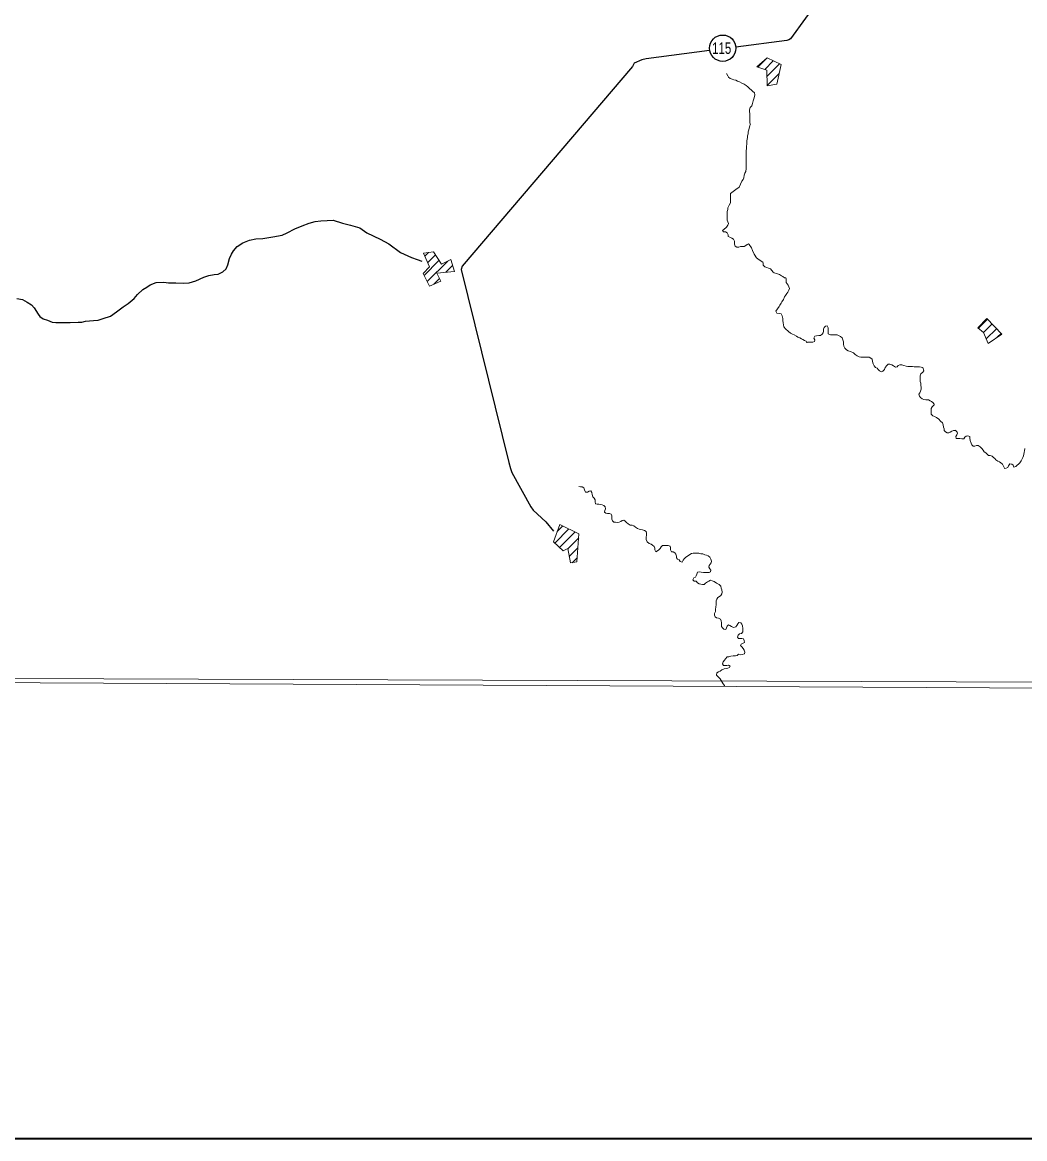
# Model space of a CAD drawing. Extents: x 553962 to 842807, y 8883888 to 9032388.
# Drawn here: x 608778 to 614885, y 8896027 to 8902830 of the extents above; entities that cross this region are included whole.
import ezdxf
from ezdxf.enums import TextEntityAlignment as Align

# ---------------------------------------------------------------- set-up
doc = ezdxf.new("R2010")
doc.units = 0
doc.header["$LTSCALE"] = 200
doc.layers.add('6', color=7, linetype='Continuous', lineweight=13)

msp = doc.modelspace()

# ---------------------------------------------------------------- linework, layer by layer
at = {"layer": '6'}
for p, q in [((613258.9, 8902557.5), (613307.3, 8902605.9)), ((613301.4, 8902543.4), (613353.5, 8902595.5)), ((613314.5, 8902500), (613391.6, 8902577)), ((613315.6, 8902444.5), (613388.7, 8902517.5)), ((611230.3, 8901404.8), (611252.2, 8901426.7)), ((611248, 8901365.9), (611294.8, 8901412.8)), ((611226.5, 8901287.9), (611316.8, 8901378.2)), ((611245.1, 8901249.9), (611370.1, 8901374.9)), ((611358.8, 8901307.1), (611399.5, 8901347.8)), ((611285.4, 8901233.7), (611320.5, 8901268.7)), ((614602.7, 8900965), (614658.4, 8901020.7)), ((614634.6, 8900940.2), (614686, 8900991.7)), ((614651.2, 8900900.4), (614713.6, 8900962.7)), ((613558.2, 8900878.2), (613557.9, 8900877)), ((614718.1, 8900910.6), (614741.2, 8900933.8)), ((612022, 8899656), (612108.6, 8899742.6)), ((612037, 8899727.6), (612070.7, 8899761.3)), ((612051.1, 8899628.6), (612146.6, 8899724)), ((612101.1, 8899622), (612167.9, 8899688.8)), ((612110.5, 8899574.8), (612163.2, 8899627.5)), ((612129.1, 8899536.8), (612158.5, 8899566.2))]:
    msp.add_line(p, q, dxfattribs=at)
at = {"layer": '6', "lineweight": 35}
msp.add_lwpolyline([(574695.3, 8924769.6), (626625.7, 8924769.6), (626625.7, 8896026.7), (574695.3, 8896026.7)], close=True, dxfattribs=at)
at = {"layer": '6'}
for points in [[(618535.2, 8909853.3), (607574.3, 8909890.7), (607543.3, 8898835.3), (618504.2, 8898795.8)], [(613253.6, 8902559.2), (613316.1, 8902613.6), (613400.9, 8902572.5), (613374.3, 8902452.9), (613315.7, 8902442), (613313.8, 8902539.4)], [(611222.2, 8901422.7), (611283.2, 8901431), (611331.4, 8901355.2), (611388, 8901384.1), (611411, 8901311.7), (611304.4, 8901302.2), (611328.1, 8901252.8), (611258.8, 8901221.7), (611220.8, 8901299.8), (611260, 8901339.5)], [(614654.9, 8901024.3), (614599.9, 8900967.2), (614634.5, 8900940.5), (614662.7, 8900873), (614745.5, 8900929.3)], [(612052.6, 8899770.2), (612169.7, 8899712.7), (612156.6, 8899541.5), (612118.4, 8899535), (612101, 8899622.7), (612072.7, 8899608.2), (612013.7, 8899663.8)]]:
    msp.add_lwpolyline(points, close=True, dxfattribs=at)
at = {"layer": '6', "lineweight": 25}
for points in [[(614884.3, 8904031.6), (614289.5, 8903510.2), (613661, 8902994.8), (613641.6, 8902983.7), (613458.3, 8902730.3), (613448.1, 8902723.2), (613436.9, 8902720.2), (613124.7, 8902678.9)], [(612965.8, 8902657.9), (612578.6, 8902606.6), (612553.1, 8902601.6), (612506.2, 8902581.3), (612494.9, 8902560.9), (611458.3, 8901343.3), (611451.1, 8901322.9), (611742.2, 8900146.7), (611753.3, 8900110), (611761.3, 8900086.6), (611876.7, 8899876.5), (611889.9, 8899857.1), (611968.1, 8899786.6), (612014.2, 8899728.6)], [(610201.6, 8901509.7), (610244.4, 8901511.6), (610303.5, 8901523.7), (610360.6, 8901533.8), (610391.2, 8901548), (610438.2, 8901571.4), (610483.1, 8901590.6), (610526, 8901606.9), (610561.7, 8901616), (610597.3, 8901621), (610635, 8901621.9), (610672.7, 8901623.9), (610728.7, 8901605.5), (610777.6, 8901593.2), (610834.6, 8901576.8), (610877.3, 8901548.1), (610958.6, 8901509.3), (611010.5, 8901479.6), (611082.6, 8901426.5), (611149.8, 8901396.9), (611184.3, 8901383.6), (611211.9, 8901373.9)], [(609069.8, 8901001.3), (609118.7, 8901002.2), (609140.1, 8901002.2), (609163.6, 8901008.3), (609211.5, 8901012.2), (609240, 8901014.2), (609271.6, 8901025.4), (609315.5, 8901039.6), (609352.3, 8901066), (609392.1, 8901096.5), (609423.8, 8901115.8), (609460.6, 8901147.3), (609481, 8901171.7), (609511.7, 8901202.2), (609536.2, 8901215.4), (609556.7, 8901230.7), (609593.4, 8901244.9), (609641.3, 8901246.8), (609669.8, 8901242.7), (609712.6, 8901241.6), (609761.5, 8901239.5), (609794.1, 8901241.4), (609835.9, 8901254.6), (609883.9, 8901277.9), (609914.5, 8901287.1), (609947.1, 8901294.1), (609970.6, 8901296.1), (609999.1, 8901310.3), (610019.6, 8901328.6), (610029.9, 8901353.1), (610040.2, 8901389.7), (610053.5, 8901416.2), (610064.8, 8901436.6), (610086.3, 8901463), (610122.1, 8901486.4), (610161.8, 8901501.6), (610201.6, 8901509.7)], [(608745.3, 8901147.6), (608778.9, 8901141.4), (608808.4, 8901124), (608833.8, 8901107.7), (608851.1, 8901089.3), (608874.4, 8901051.6), (608884.5, 8901036.3), (608905.9, 8901024), (608932.3, 8901014.8), (608959.8, 8901002.5), (608982.2, 8901001.5), (609069.8, 8901001.3)]]:
    msp.add_lwpolyline(points, dxfattribs=at)
at = {"layer": '6'}
for points in [[(613067.8, 8902517.8), (613076.8, 8902504.5), (613080.8, 8902495.3), (613091, 8902488.1), (613102.1, 8902483.9), (613113.3, 8902479.8), (613124.5, 8902476.7), (613134.6, 8902471.5), (613147.8, 8902467.4), (613162, 8902460.2), (613175.2, 8902452.9), (613187.3, 8902444.7), (613197.4, 8902436.5), (613210.6, 8902425.2), (613218.7, 8902418.1), (613227.7, 8902409.8), (613238.9, 8902399.6), (613241.8, 8902388.4), (613236.6, 8902370.1), (613231.4, 8902351.8), (613226.2, 8902335.5), (613223.1, 8902321.3), (613212.8, 8902310.1), (613208.7, 8902296.9), (613208.6, 8902286.7), (613210.5, 8902272.5), (613210.5, 8902262.3), (613210.3, 8902245), (613210.2, 8902232.7), (613210.2, 8902220.5), (613213.1, 8902210.3), (613215.1, 8902208.5)], [(613214.9, 8902208.8), (613211.4, 8902200.8), (613205.1, 8902175.3), (613200.9, 8902162.1), (613199.8, 8902149.9), (613195.7, 8902138.7), (613195.6, 8902128.6), (613192.4, 8902108.2), (613192.3, 8902087.8), (613191.2, 8902074.6), (613191.1, 8902061.3), (613187.9, 8902046.1), (613187.8, 8902034.9), (613187.8, 8902023.7), (613188.9, 8902003.7), (613187.6, 8901993.1), (613187.5, 8901980.9), (613187.4, 8901965.6), (613188.3, 8901951.4), (613189.2, 8901939.2), (613185.5, 8901921), (613180.9, 8901911.7), (613176.7, 8901899.5), (613173.6, 8901882.2), (613169.4, 8901872.1), (613162.2, 8901861.9), (613144.8, 8901826.3), (613125.2, 8901810.6), (613093.6, 8901785.9), (613093.5, 8901775.8), (613092.4, 8901763.5), (613092.3, 8901753.4), (613092.2, 8901743.2), (613092.2, 8901730.9), (613083.9, 8901714.7), (613076.7, 8901698.5), (613075.6, 8901688.3), (613072.5, 8901676.1), (613072.4, 8901663.9), (613072.2, 8901647.6), (613072.2, 8901635.3), (613072.1, 8901625.2), (613077.1, 8901614.9), (613080.1, 8901604.7), (613077, 8901594.6), (613067.7, 8901581.4), (613051.4, 8901568.2), (613043.2, 8901562.2), (613050.2, 8901554), (613062.5, 8901553.9), (613071.6, 8901546.7), (613077.6, 8901534.5), (613078.5, 8901524.3), (613088.7, 8901520.2), (613100.8, 8901515), (613111, 8901508.8), (613117, 8901495.5), (613116.8, 8901478.2), (613120.8, 8901464.9), (613131, 8901459.8), (613143.2, 8901460.7), (613153.4, 8901463.7), (613164.6, 8901463.7), (613175.8, 8901464.6), (613186, 8901470.7), (613194.2, 8901476.7), (613203.3, 8901480.7)], [(613203.3, 8901480.7), (613207.5, 8901475.3), (613220.8, 8901455), (613227, 8901438.8), (613237.3, 8901416.4), (613250.6, 8901395.1), (613268, 8901382.9), (613288.8, 8901367.7)], [(613288.8, 8901367.7), (613291.1, 8901363.5), (613291.6, 8901350.4), (613301.8, 8901340.3), (613337.5, 8901327.3), (613352.9, 8901307), (613358, 8901304), (613372.2, 8901300), (613390.6, 8901292.9), (613402.8, 8901284.9)], [(613402.8, 8901284.9), (613412.2, 8901280.8), (613421.3, 8901273.6), (613429.4, 8901273), (613432.2, 8901268.8), (613432.3, 8901265)], [(613369.1, 8901070.7), (613389.4, 8901097.2), (613393.5, 8901107.3), (613400.7, 8901118.5), (613405.9, 8901127.6), (613415.1, 8901141.8), (613422.3, 8901156.1), (613428.5, 8901166.2), (613436.8, 8901178.4), (613442.9, 8901186.5), (613449.1, 8901197.7), (613452.2, 8901207.8), (613449.2, 8901219), (613444.2, 8901228.2), (613438.2, 8901236.4), (613431.1, 8901243.6), (613431.2, 8901254.8), (613432.3, 8901265), (613432.3, 8901265)], [(613557.9, 8900877), (613552.9, 8900886.2), (613543.8, 8900891.3), (613533.6, 8900897.5), (613524.5, 8900901.7), (613515.4, 8900906.8), (613503.2, 8900910.9), (613494.1, 8900917.1), (613480.9, 8900925.3), (613469.8, 8900930.5), (613458.6, 8900934.7), (613445.5, 8900945.9), (613428.3, 8900962.3), (613418.2, 8900974.6), (613415.3, 8900985.9), (613413.3, 8900999.1), (613412.4, 8901013.4), (613411.5, 8901025.6), (613408.5, 8901040.9), (613401.5, 8901054.2), (613390.3, 8901055.3), (613375.1, 8901058.4), (613369.1, 8901070.7), (613369.1, 8901072), (613369.1, 8901070.7)], [(614265.5, 8900726.8), (614255.3, 8900728.9), (614245.2, 8900731), (614233, 8900731.1), (614222.8, 8900731.2), (614212.6, 8900731.2), (614201.5, 8900732.3), (614187.2, 8900733.4), (614174, 8900733.5), (614162.8, 8900733.6), (614148.6, 8900737.8), (614136.4, 8900741.9), (614125.2, 8900742), (614115.1, 8900739), (614108.9, 8900730.9), (614097.7, 8900727.9), (614086.6, 8900736.1), (614076.4, 8900742.3), (614064.3, 8900747.5), (614054.1, 8900747.5), (614044.9, 8900739.4), (614034.6, 8900727.3), (614031.5, 8900715.1), (614021.2, 8900703.9), (614012.1, 8900699.9), (613999.9, 8900706.1), (613992.8, 8900714.3), (613985.8, 8900721.5), (613976.6, 8900725.6), (613968.6, 8900735.8), (613961.5, 8900748.1), (613957.6, 8900762.4), (613955.6, 8900776.7), (613948.6, 8900783.8), (613937.4, 8900790), (613924.2, 8900790.1), (613914, 8900790.2), (613899.8, 8900790.3), (613886.6, 8900790.3), (613876.4, 8900792.4), (613865.3, 8900797.6), (613853.1, 8900804.8), (613843, 8900816.1), (613824.8, 8900823.3), (613810.6, 8900827.5), (613799.4, 8900834.7), (613790.3, 8900844.9), (613783.3, 8900856.2), (613780.3, 8900869.4), (613780.4, 8900882.7), (613777.5, 8900894.9), (613772.5, 8900906.2), (613763.4, 8900914.4), (613751.2, 8900920.6), (613742.1, 8900924.7), (613728.9, 8900925.8), (613714.6, 8900925.9), (613701.4, 8900926), (613687.2, 8900932.2), (613687.3, 8900944.4), (613687.4, 8900957.6), (613687.5, 8900968.8), (613681.5, 8900980.1), (613671.3, 8900979.1), (613664.1, 8900971), (613660, 8900960.8), (613658.9, 8900948.6), (613657.8, 8900938.5), (613650.6, 8900929.3), (613641.4, 8900922.3), (613630.2, 8900921.3), (613617, 8900920.4), (613605.8, 8900917.4), (613600.6, 8900905.2), (613605.6, 8900896), (613604.5, 8900885.8), (613595.3, 8900881.8), (613584.1, 8900880.9), (613573, 8900880.9), (613562.8, 8900880), (613558.2, 8900878.2)], [(614333.4, 8900497.8), (614333.4, 8900503.9), (614326.3, 8900512.1), (614318.2, 8900518.3), (614309.1, 8900523.4), (614299, 8900528.6), (614282.7, 8900528.7), (614270.5, 8900531.8), (614261.4, 8900535.9), (614251.3, 8900543.1), (614244.2, 8900552.3), (614241.2, 8900563.6), (614245.4, 8900572.7), (614249.5, 8900581.8), (614254.7, 8900594), (614254.8, 8900605.2), (614252.8, 8900619.5), (614251.9, 8900630.7), (614247.9, 8900640.9), (614248, 8900652.1), (614249.1, 8900664.3), (614249.2, 8900676.6), (614253.3, 8900688.8), (614264.6, 8900698.9), (614270.7, 8900707), (614265.5, 8900726.8)], [(614664.7, 8900190.6), (614656.6, 8900197.8), (614648.6, 8900206), (614637.4, 8900213.2), (614631.4, 8900223.4), (614624.3, 8900233.6), (614613.2, 8900243.9), (614602.1, 8900251.1), (614590.9, 8900251.2), (614580.7, 8900247.2), (614570.5, 8900247.2), (614562.5, 8900255.4), (614559.5, 8900265.6), (614553.5, 8900281.9), (614551.6, 8900296.2), (614551.6, 8900306.4), (614539.4, 8900310.6), (614529.3, 8900308.6), (614521.1, 8900301.5), (614513.9, 8900292.4), (614502.7, 8900292.5), (614490.5, 8900293.6), (614480.3, 8900293.6), (614468.1, 8900293.7), (614466.2, 8900305.9), (614471.3, 8900316.1), (614475.5, 8900326.2), (614473.7, 8900333.3), (614468.3, 8900338.8), (614465.5, 8900344.2), (614462.8, 8900341.5), (614452.2, 8900342.7), (614442, 8900338.7), (614431.8, 8900332.6), (614422.6, 8900327.6), (614412.4, 8900328.7), (614402.3, 8900333.8), (614395.2, 8900342), (614394.3, 8900352.2), (614391.3, 8900363.4), (614389.4, 8900376.7), (614383.4, 8900388.9), (614372.3, 8900400.2), (614361.2, 8900411.5), (614347, 8900420.8), (614334.8, 8900426.9), (614325.7, 8900432.1), (614315.6, 8900442.3), (614315.7, 8900454.6), (614315.8, 8900464.7), (614315.8, 8900477), (614321, 8900486.1), (614329.2, 8900495.2), (614333.4, 8900497.8)], [(614761.4, 8900112.2), (614760.8, 8900116.7), (614753.8, 8900128.9), (614749.8, 8900138.1), (614740.7, 8900146.3), (614731.6, 8900151.5), (614721.4, 8900155.6), (614710.3, 8900162.8), (614704.2, 8900171), (614695.1, 8900178.2), (614686, 8900185.4), (614674.9, 8900190.5), (614664.7, 8900190.6)], [(614885.7, 8900232.8), (614885.7, 8900230.9), (614884.6, 8900220.8), (614882.5, 8900208.6), (614880.4, 8900197.4), (614878.3, 8900187.2), (614874.1, 8900178.1), (614867.9, 8900165.9), (614862.8, 8900156.8), (614854.6, 8900144.6), (614847.4, 8900137.5), (614839.2, 8900130.4), (614831, 8900123.3), (614819.8, 8900119.3), (614814.8, 8900130.6), (614807.7, 8900137.8), (614794.5, 8900138.8), (614787.3, 8900127.7), (614783.2, 8900116.5), (614772, 8900112.5), (614762.4, 8900110.6), (614761.4, 8900112.2)], [(612169.4, 8900000.7), (612179.1, 8899998.2), (612189.2, 8899998.2), (612198.4, 8899993), (612202.4, 8899980.8), (612208.4, 8899967.5), (612220.6, 8899966.4), (612230.8, 8899972.4), (612242, 8899974.4), (612249, 8899964.2), (612251, 8899951.9), (612254, 8899938.7), (612263.1, 8899930.5), (612269.1, 8899919.2), (612269, 8899907), (612270.9, 8899894.8), (612281.1, 8899892.7), (612291.3, 8899892.6), (612301.4, 8899891.5), (612311.6, 8899889.4), (612320.7, 8899885.3), (612328.8, 8899877.1), (612330.8, 8899865.9), (612326.6, 8899855.7), (612325.5, 8899845.5), (612333.6, 8899839.3), (612343.8, 8899836.2), (612356, 8899836.2), (612365.1, 8899832), (612369.1, 8899822.8), (612369.1, 8899812.6), (612369, 8899801.4), (612374, 8899791.2), (612381.1, 8899784), (612391.2, 8899782.9), (612403.4, 8899781.8), (612414.6, 8899784.8), (612424.8, 8899787.8), (612433, 8899793.9), (612443.2, 8899796.9), (612451.3, 8899790.7), (612458.4, 8899782.5), (612468.5, 8899773.3), (612480.6, 8899765.1), (612493.8, 8899765), (612504, 8899760.8), (612514.1, 8899752.6), (612526.2, 8899745.4), (612535.4, 8899741.3), (612545.5, 8899738.2), (612556.7, 8899738.1), (612567.9, 8899733.9), (612578, 8899726.7), (612581, 8899716.5), (612580.9, 8899704.3), (612579.8, 8899692.1), (612578.7, 8899678.8), (612585.7, 8899664.5), (612597.8, 8899654.3), (612609, 8899649.1), (612617.1, 8899642.9), (612628.2, 8899634.7), (612632.2, 8899625.5), (612632.2, 8899614.3), (612638.2, 8899603.1), (612648.4, 8899609.1), (612655.6, 8899616.2), (612663.8, 8899623.3), (612669.9, 8899633.4), (612679.2, 8899642.6), (612691.4, 8899642.5), (612702.5, 8899641.4), (612713.7, 8899641.3), (612724.9, 8899637.2), (612727.9, 8899626.9), (612727.8, 8899614.7), (612732.8, 8899602.5), (612743, 8899602.4), (612753.1, 8899597.2), (612759.1, 8899589.1), (612763.1, 8899576.8), (612764.1, 8899566.6), (612770.1, 8899558.4), (612779.2, 8899553.3), (612786.3, 8899545.1), (612797.5, 8899540.9), (612804.7, 8899552.1), (612810.8, 8899561.2), (612819, 8899568.3), (612826.2, 8899575.4), (612836.4, 8899580.4), (612844.6, 8899587.5), (612854.8, 8899592.5), (612866, 8899595.5), (612877.2, 8899595.4), (612890.4, 8899595.3), (612900.6, 8899594.3), (612912.8, 8899590.1), (612925, 8899590), (612936.1, 8899584.9), (612946.3, 8899581.8)], [(612946.3, 8899581.8), (612957.4, 8899578.6), (612966.5, 8899570.4), (612972.6, 8899558.2), (612976.5, 8899546.9), (612975.5, 8899535.7), (612969.3, 8899527.6), (612962.1, 8899520.5), (612961, 8899510.3), (612966, 8899499.1), (612973.1, 8899490.9), (612971.8, 8899480.8), (612962.8, 8899477.7), (612950.6, 8899477.8), (612939.5, 8899477.9), (612929.3, 8899477.9), (612915.1, 8899480.1), (612903.9, 8899481.2), (612891.6, 8899478.2), (612888.5, 8899467), (612884.4, 8899456.8), (612880.2, 8899447.7), (612869, 8899443.7), (612863.8, 8899431.5), (612871.9, 8899424.3), (612883.1, 8899424.2), (612891.2, 8899414), (612901.3, 8899408.8), (612911.5, 8899406.7), (612921.7, 8899404.6), (612931.8, 8899404.6), (612940, 8899412.7), (612952.3, 8899419.7), (612961.5, 8899424.8), (612971.7, 8899429.8), (612981.8, 8899425.7), (612993, 8899422.5), (613007.2, 8899412.2), (613024.4, 8899403), (613033.5, 8899394.8), (613035.4, 8899382.5), (613040.4, 8899371.3), (613041.4, 8899358), (613040.3, 8899347.8), (613033.1, 8899337.7), (613024.9, 8899330.6), (613014.7, 8899324.6), (613009.5, 8899315.4), (613006.4, 8899305.3), (613005.3, 8899295.1), (613005.2, 8899280.8), (613004.1, 8899268.6), (613001, 8899252.3), (613000.9, 8899240.1), (612995.7, 8899227.9), (612994.6, 8899216.7), (612999.6, 8899207.5), (613007.7, 8899201.3), (613018.9, 8899199.2), (613031.1, 8899192), (613036.1, 8899182.8), (613038, 8899170.6), (613038, 8899158.4), (613038.9, 8899148.2), (613045, 8899140), (613053, 8899130.8), (613064.2, 8899130.7), (613069.4, 8899139.8), (613073.5, 8899151), (613079.7, 8899159.1), (613088.8, 8899155), (613098.9, 8899148.8), (613112.1, 8899141.6), (613124.3, 8899145.6), (613130.5, 8899154.7), (613136.7, 8899163.8), (613142.8, 8899172), (613155, 8899170.9), (613161.1, 8899162.7), (613165.1, 8899151.4), (613168, 8899136.1), (613167.9, 8899125.9), (613167.9, 8899115.8), (613160.7, 8899104.6), (613148.5, 8899102.7), (613140.3, 8899095.6), (613136.1, 8899083.4), (613142.2, 8899075.2), (613152.3, 8899074.1), (613162.5, 8899074), (613172.7, 8899072.9), (613176.7, 8899061.7), (613177.6, 8899051.5), (613169.4, 8899045.5), (613158.2, 8899040.4), (613154.1, 8899031.3), (613161.1, 8899024.1), (613170.2, 8899014.9), (613175.2, 8899003.7), (613179.2, 8898992.4), (613177.1, 8898981.2)], [(613177.1, 8898981.2), (613164.9, 8898978.2), (613152.7, 8898976.3), (613141.5, 8898978.4), (613133.3, 8898971.3), (613123.1, 8898969.3), (613108.9, 8898968.4), (613095.6, 8898967.5), (613083.4, 8898963.5), (613073.2, 8898962.5), (613063, 8898951.4), (613055.8, 8898942.3), (613047.6, 8898932.1), (613043.5, 8898921), (613049.5, 8898910.7), (613059.7, 8898910.7), (613069.8, 8898910.6), (613081, 8898911.6), (613090.1, 8898906.4), (613086, 8898897.2), (613076.8, 8898893.2), (613066.6, 8898891.3), (613054.4, 8898889.3), (613040.1, 8898883.3), (613029.9, 8898875.2), (613020.7, 8898871.2), (613009.5, 8898865.2), (613008.4, 8898851.9), (613020.5, 8898839.6), (613029.6, 8898829.4), (613035.6, 8898818.1), (613042.7, 8898807.9), (613048.7, 8898797.7), (613056.8, 8898789.4), (613057.8, 8898788.4)], [(574695.3, 8898953.2), (596544.3, 8898870.4), (626625.7, 8898710.8)]]:
    msp.add_lwpolyline(points, dxfattribs=at)
at = {"layer": '6', "lineweight": 25}
msp.add_circle((613045.3, 8902672.4), 80.3, dxfattribs=at)

# ---------------------------------------------------------------- texts
at = {"layer": '6', "width": 0.75}
msp.add_text('115', height=70, dxfattribs=at).set_placement((613038.9, 8902637.7), align=Align.CENTER)

doc.saveas('drawing.dxf')
